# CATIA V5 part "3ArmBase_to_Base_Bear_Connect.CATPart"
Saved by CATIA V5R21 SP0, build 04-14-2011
Part number: ArmBase_to_Base_Bear_Connect
Bounding box of the stored display mesh (mm): x 0 to 8, y -32 to 32, z -25.5 to 25.5
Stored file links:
  F:\教程\Robotic_Arm_Arduino_Kinect\机械臂CAD\Arm_Detailed_Design_Assembly\Base_to_Base_Bear_Connect.CATPart
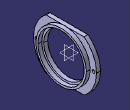
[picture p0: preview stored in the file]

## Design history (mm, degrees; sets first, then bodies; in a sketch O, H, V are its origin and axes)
Body1 (main body)
  Sketch1 on yz-plane, origin (0, 0, 0), H (0, 1, 0), V (0, 0, 1)
    circle A1 centre (0, 0) radius 32
    circle A2 centre (0, 0) radius 21.5
    radius A2 = 21.5
    radius A1 = 32
  Pad1: profile Sketch1, direction (1, 0, 0), length 4
  Sketch2 on end face of Pad1, origin (4, 0, 0), H (0, 1, 0), V (0, 0, 1)
    circle A1 centre (0, 0) radius 23.5
    circle A2 centre (0, 0) radius 25.5
    radius A2 = 25.5
    radius A1 = 23.5
  Pad2: profile Sketch2, direction (1, 0, 0), length 4
  Sketch3 on start face of Pad1, origin (0, 0, 0), H (0, -1, 0), V (0, 0, 1)
    circle A1 centre (29, 0) radius 1.5
    point P1 (29, 0)
    point P2 (30.5, 0)
    circle A2 centre (-29, 0) radius 1.5
    point P3 (-29, 0)
    line L1 (-30.0408, 34.0267) -> (31.4698, 34.0267)
    line L2 (31.4698, 34.0267) -> (31.4698, 25.5)
    line L3 (31.4698, 25.5) -> (-30.0408, 25.5)
    line L4 (-30.0408, 25.5) -> (-30.0408, 34.0267)
    reference projected circle E1 centre (0, 0) radius 25.5 from edge [end face of Pad1 | face of Pad2 from Sketch2.A2]
    line L5 (26.753, -25.5) -> (-25.9884, -25.5)
    line L6 (-25.9884, -25.5) -> (-25.9884, -39.4596)
    line L7 (-25.9884, -39.4596) -> (26.753, -39.4596)
    line L8 (26.753, -39.4596) -> (26.753, -25.5)
    reference projected circle E2 centre (0, 0) radius 25.5 from edge [end face of Pad1 | face of Pad2 from Sketch2.A2]
    radius A1 = 1.5
    radius A2 = 1.5
    distance V P1 = 29
    distance V P3 = 29
    coincidence: P1 H, A1 P2, P2 H, P3 H
    horizontal: L1 H, L3 H, L5 H, L7 H
    vertical: L2 V, L4 V, L6 V, L8 V
    tangency: E1 L3, L5 E2
  Pocket1: profile Sketch3, direction (1, 0, 0), through (limit type 3)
